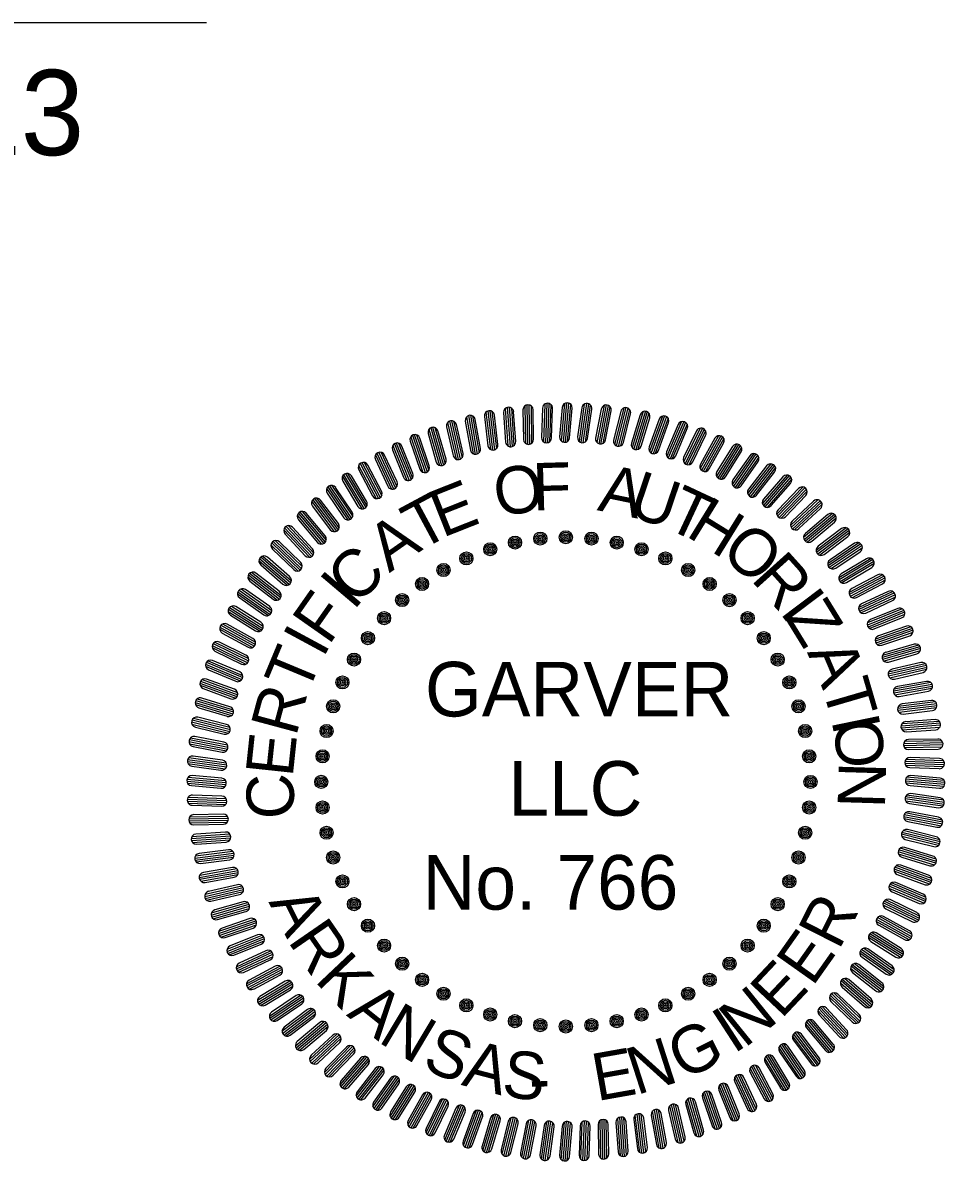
# Model space of a CAD drawing. Extents: x 1373884 to 1376992, y 1168426 to 1170473.
# Drawn here: x 1376215 to 1376507, y 1168433.5 to 1168793.9 of the extents above; entities that cross this region are included whole.
import ezdxf

# ---------------------------------------------------------------- set-up
doc = ezdxf.new("R2010")
doc.units = 0
for name, color, linetype in [('G-ANNO-STMP', 7, 'Continuous'), ('G-ANNO-TEXT', 7, 'Continuous'), ('R_Draft', 7, 'Continuous')]:
    doc.layers.add(name, color=color, linetype=linetype)

# ---------------------------------------------------------------- blocks, each defined once
blk = doc.blocks.new('SEALDO')
at = {"layer": 'G-ANNO-TEXT'}
for radius in [0.0396, 0.0305, 0.0213, 0.0122, 0.00305]:
    blk.add_circle((1.403, -0.4559), radius, dxfattribs=at)
blk = doc.blocks.new('SEALRI')
at = {"layer": 'G-ANNO-TEXT'}
for p, q in [((-0.0083, 2.2815), (-0.0281, 2.0555)), ((0.0043, 2.2859), (-0.0164, 2.049)), ((0.0164, 2.2848), (-0.0043, 2.0479)), ((0.0281, 2.2783), (0.0083, 2.0523)), ((-0.0226, 2.2583), (-0.0381, 2.0809)), ((0.0226, 2.0756), (0.0381, 2.253))]:
    blk.add_line(p, q, dxfattribs=at)
for centre, start, end in [((0.0078, 2.2556), 355, 175), ((-0.0078, 2.0782), 175, 355)]:
    blk.add_arc(centre, 0.0305, start, end, dxfattribs=at)

msp = doc.modelspace()

# ---------------------------------------------------------------- linework, layer by layer
at = {"layer": 'R_Draft'}
msp.add_line((1376273.16, 1168793.87), (1375919.94, 1168793.87), dxfattribs=at)

# ---------------------------------------------------------------- block references
at = {"layer": 'G-ANNO-STMP'}
for name, xscale, yscale, rotation in [('SEALRI', 52.492405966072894, 52.49240596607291, 9), ('SEALRI', 52.492405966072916, 52.49240596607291, 6), ('SEALRI', 52.492405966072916, 52.492405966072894, 3.0000000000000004), ('SEALRI', 52.49240596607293, 52.49240596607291, -2.9999999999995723), ('SEALRI', 52.4924059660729, 52.49240596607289, -5.9999999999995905), ('SEALRI', 52.492405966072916, 52.49240596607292, -8.999999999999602), ('SEALRI', 52.492405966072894, 52.4924059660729, 18), ('SEALRI', 52.4924059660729, 52.4924059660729, 15.000000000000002), ('SEALRI', 52.492405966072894, 52.492405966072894, 12.000000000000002), ('SEALRI', 52.492405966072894, 52.492405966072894, -11.999999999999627), ('SEALRI', 52.4924059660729, 52.492405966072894, -14.999999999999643), ('SEALRI', 52.4924059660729, 52.4924059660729, -17.999999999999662), ('SEALRI', 52.49240596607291, 52.4924059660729, 20.99999999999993), ('SEALRI', 52.4924059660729, 52.492405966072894, -20.999999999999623), ('SEALRI', 52.492405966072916, 52.492405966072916, 26.999999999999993), ('SEALRI', 52.49240596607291, 52.4924059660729, 23.99999999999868), ('SEALRI', 52.492405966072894, 52.4924059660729, -23.99999999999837), ('SEALRI', 52.492405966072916, 52.49240596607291, -26.9999999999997), ('SEALRI', 52.4924059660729, 52.492405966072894, 30.00000000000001), ('SEALRI', 52.4924059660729, 52.49240596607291, -29.99999999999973), ('SEALRI', 52.4924059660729, 52.492405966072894, 33), ('SEALRI', 52.4924059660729, 52.49240596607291, -32.999999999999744), ('SEALRI', 52.4924059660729, 52.492405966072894, 36), ('SEALRI', 52.4924059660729, 52.492405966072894, -35.999999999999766), ('SEALRI', 52.49240596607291, 52.4924059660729, 38.999999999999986), ('SEALRI', 52.4924059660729, 52.4924059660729, -38.99999999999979), ('SEALRI', 52.49240596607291, 52.4924059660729, 41.999999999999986), ('SEALRI', 52.4924059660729, 52.4924059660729, -41.99999999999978), ('SEALRI', 52.4924059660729, 52.492405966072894, 44.999999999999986), ('SEALRI', 52.49240596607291, 52.4924059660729, -44.99999999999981), ('SEALRI', 52.492405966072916, 52.49240596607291, 47.99999999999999), ('SEALDO', 52.4924059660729, 52.49240596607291, 113.99999999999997), ('SEALDO', 52.4924059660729, 52.49240596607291, 107.99999999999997), ('SEALDO', 52.4924059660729, 52.49240596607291, 101.99999999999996), ('SEALRI', 52.49240596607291, 52.4924059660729, -47.99999999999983), ('SEALRI', 52.49240596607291, 52.4924059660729, 50.99999999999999), ('SEALDO', 52.492405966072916, 52.492405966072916, 125.99999999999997), ('SEALDO', 52.492405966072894, 52.4924059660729, 119.99999999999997), ('SEALDO', 52.492405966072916, 52.49240596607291, 95.99999999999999), ('SEALDO', 52.49240596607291, 52.4924059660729, 90), ('SEALRI', 52.492405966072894, 52.4924059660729, -50.99999999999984), ('SEALRI', 52.4924059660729, 52.492405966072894, 54), ('SEALDO', 52.492405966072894, 52.49240596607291, 131.99999999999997), ('SEALDO', 52.492405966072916, 52.492405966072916, 83.99999999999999), ('SEALRI', 52.4924059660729, 52.4924059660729, -53.99999999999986), ('SEALDO', 52.4924059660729, 52.49240596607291, 138), ('SEALDO', 52.492405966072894, 52.4924059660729, 77.99999999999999), ('SEALRI', 52.49240596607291, 52.492405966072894, 56.99999999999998), ('SEALDO', 52.492405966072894, 52.4924059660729, 144), ('SEALDO', 52.492405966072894, 52.4924059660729, 72), ('SEALRI', 52.49240596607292, 52.49240596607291, -56.999999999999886), ('SEALRI', 52.492405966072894, 52.4924059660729, 59.999999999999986), ('SEALRI', 52.4924059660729, 52.4924059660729, -59.99999999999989), ('SEALDO', 52.49240596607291, 52.4924059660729, 150), ('SEALDO', 52.49240596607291, 52.49240596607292, 66.00000000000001), ('SEALRI', 52.492405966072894, 52.49240596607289, 63), ('SEALDO', 52.4924059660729, 52.49240596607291, 156.00000000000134), ('SEALDO', 52.49240596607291, 52.4924059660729, 60.00000000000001), ('SEALRI', 52.49240596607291, 52.492405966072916, -62.99999999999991), ('SEALRI', 52.49240596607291, 52.4924059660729, 65.99999999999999), ('SEALRI', 52.49240596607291, 52.49240596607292, -65.99999999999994), ('SEALDO', 52.492405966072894, 52.49240596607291, 162.00000000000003), ('SEALDO', 52.4924059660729, 52.492405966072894, 54), ('SEALRI', 52.49240596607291, 52.4924059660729, 68.99999999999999), ('SEALRI', 52.49240596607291, 52.4924059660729, -68.99999999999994), ('SEALRI', 52.492405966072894, 52.4924059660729, 72), ('SEALDO', 52.49240596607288, 52.4924059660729, 168.00000000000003), ('SEALDO', 52.49240596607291, 52.4924059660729, 48.000000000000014), ('SEALRI', 52.4924059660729, 52.4924059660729, -71.99999999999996), ('SEALRI', 52.4924059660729, 52.49240596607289, 75.00000000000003), ('SEALDO', 52.492405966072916, 52.49240596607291, 174.00000000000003), ('SEALDO', 52.492405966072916, 52.49240596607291, 42.00000000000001), ('SEALRI', 52.49240596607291, 52.4924059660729, -74.99999999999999), ('SEALRI', 52.492405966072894, 52.49240596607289, 78.00000000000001), ('SEALDO', 52.49240596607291, 52.4924059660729, -179.99999999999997), ('SEALDO', 52.4924059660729, 52.492405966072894, 36), ('SEALRI', 52.492405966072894, 52.492405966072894, -78), ('SEALRI', 52.492405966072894, 52.49240596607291, 81), ('SEALDO', 52.49240596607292, 52.49240596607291, -173.99999999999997), ('SEALDO', 52.49240596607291, 52.4924059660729, 29.999999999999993), ('SEALRI', 52.492405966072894, 52.49240596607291, -81.00000000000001), ('SEALRI', 52.492405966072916, 52.49240596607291, 84.00000000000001), ('SEALRI', 52.492405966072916, 52.49240596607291, -84.00000000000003), ('SEALDO', 52.492405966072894, 52.4924059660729, -167.99999999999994), ('SEALDO', 52.49240596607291, 52.4924059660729, 23.99999999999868), ('SEALRI', 52.4924059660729, 52.49240596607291, 87.00000000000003), ('SEALRI', 52.4924059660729, 52.4924059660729, -87.00000000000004), ('SEALRI', 52.49240596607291, 52.4924059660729, 90.00000000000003), ('SEALDO', 52.4924059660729, 52.492405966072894, -161.99999999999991), ('SEALDO', 52.492405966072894, 52.4924059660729, 18), ('SEALRI', 52.49240596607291, 52.4924059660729, -90.00000000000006), ('SEALRI', 52.492405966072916, 52.492405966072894, 93), ('SEALRI', 52.492405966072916, 52.49240596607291, -93.00000000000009), ('SEALDO', 52.4924059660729, 52.4924059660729, -156.00000000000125), ('SEALDO', 52.492405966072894, 52.492405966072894, 12.000000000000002), ('SEALRI', 52.492405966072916, 52.492405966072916, 96.00000000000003), ('SEALRI', 52.4924059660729, 52.492405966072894, -96.0000000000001), ('SEALRI', 52.49240596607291, 52.492405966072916, 99.00000000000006), ('SEALDO', 52.4924059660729, 52.49240596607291, -149.99999999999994), ('SEALDO', 52.492405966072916, 52.49240596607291, 6), ('SEALRI', 52.49240596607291, 52.492405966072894, -99.00000000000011), ('SEALRI', 52.492405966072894, 52.49240596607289, 102.00000000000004), ('SEALDO', 52.492405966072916, 52.49240596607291, -143.99999999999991), ('SEALRI', 52.492405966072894, 52.492405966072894, -102.00000000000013), ('SEALRI', 52.49240596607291, 52.4924059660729, 105.00000000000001), ('SEALRI', 52.49240596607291, 52.4924059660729, -105.00000000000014), ('SEALDO', 52.492405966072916, 52.49240596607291, -137.9999999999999), ('SEALDO', 52.4924059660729, 52.4924059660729, -6.000000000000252), ('SEALRI', 52.4924059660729, 52.4924059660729, 108.00000000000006), ('SEALRI', 52.49240596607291, 52.492405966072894, -108.00000000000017), ('SEALRI', 52.4924059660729, 52.492405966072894, 111.00000000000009), ('SEALDO', 52.4924059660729, 52.49240596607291, -131.99999999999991), ('SEALDO', 52.492405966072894, 52.492405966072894, -12.000000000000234), ('SEALRI', 52.4924059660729, 52.49240596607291, -111.00000000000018), ('SEALRI', 52.49240596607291, 52.492405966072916, 114.00000000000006), ('SEALDO', 52.4924059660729, 52.49240596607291, -125.9999999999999), ('SEALDO', 52.492405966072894, 52.4924059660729, -18.000000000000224), ('SEALRI', 52.49240596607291, 52.492405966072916, -114.0000000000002), ('SEALRI', 52.4924059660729, 52.49240596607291, 117.00000000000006), ('SEALRI', 52.49240596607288, 52.4924059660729, -117.00000000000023), ('SEALDO', 52.4924059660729, 52.4924059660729, -119.99999999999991), ('SEALDO', 52.49240596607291, 52.492405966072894, -23.999999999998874), ('SEALRI', 52.492405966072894, 52.4924059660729, 120.00000000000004), ('SEALDO', 52.4924059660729, 52.492405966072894, -30.00000000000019), ('SEALRI', 52.4924059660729, 52.4924059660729, -120.00000000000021), ('SEALRI', 52.4924059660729, 52.492405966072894, 123.00000000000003), ('SEALDO', 52.49240596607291, 52.492405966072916, -113.99999999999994), ('SEALRI', 52.492405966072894, 52.49240596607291, -123.00000000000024), ('SEALRI', 52.4924059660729, 52.49240596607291, 126.00000000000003), ('SEALDO', 52.4924059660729, 52.4924059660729, -107.99999999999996), ('SEALDO', 52.4924059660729, 52.4924059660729, -36.00000000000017), ('SEALRI', 52.4924059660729, 52.4924059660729, -126.00000000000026), ('SEALDO', 52.492405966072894, 52.49240596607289, -101.99999999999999), ('SEALDO', 52.4924059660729, 52.492405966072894, -42.00000000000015), ('SEALRI', 52.49240596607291, 52.4924059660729, 129.00000000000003), ('SEALDO', 52.492405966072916, 52.49240596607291, -96), ('SEALDO', 52.49240596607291, 52.492405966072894, -48.00000000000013), ('SEALRI', 52.492405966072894, 52.4924059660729, -129.00000000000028), ('SEALRI', 52.4924059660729, 52.4924059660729, 132), ('SEALDO', 52.49240596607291, 52.4924059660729, -90.00000000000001), ('SEALDO', 52.4924059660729, 52.4924059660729, -54.000000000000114), ('SEALRI', 52.49240596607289, 52.4924059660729, -132.00000000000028), ('SEALRI', 52.4924059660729, 52.49240596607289, 135), ('SEALDO', 52.492405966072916, 52.49240596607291, -84.00000000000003), ('SEALDO', 52.4924059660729, 52.49240596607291, -78.00000000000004), ('SEALDO', 52.4924059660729, 52.49240596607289, -72.00000000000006), ('SEALDO', 52.492405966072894, 52.49240596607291, -66.00000000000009), ('SEALDO', 52.4924059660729, 52.49240596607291, -60.0000000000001), ('SEALRI', 52.492405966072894, 52.4924059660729, -135.00000000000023), ('SEALRI', 52.4924059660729, 52.49240596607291, 138), ('SEALRI', 52.4924059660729, 52.492405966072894, -138.00000000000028), ('SEALRI', 52.492405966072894, 52.4924059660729, 140.99999999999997), ('SEALRI', 52.4924059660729, 52.4924059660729, -141.0000000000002), ('SEALRI', 52.492405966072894, 52.4924059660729, 144), ('SEALRI', 52.49240596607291, 52.49240596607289, -144.00000000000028), ('SEALRI', 52.4924059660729, 52.492405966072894, 146.99999999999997), ('SEALRI', 52.4924059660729, 52.49240596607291, -147.00000000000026), ('SEALRI', 52.4924059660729, 52.49240596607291, 149.99999999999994), ('SEALRI', 52.49240596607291, 52.492405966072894, -150.00000000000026), ('SEALRI', 52.492405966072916, 52.49240596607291, 152.99999999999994), ('SEALRI', 52.4924059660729, 52.49240596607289, 156.00000000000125), ('SEALRI', 52.492405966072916, 52.49240596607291, -156.00000000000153), ('SEALRI', 52.4924059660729, 52.49240596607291, -153.00000000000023), ('SEALRI', 52.4924059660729, 52.4924059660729, 159), ('SEALRI', 52.4924059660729, 52.49240596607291, -159.00000000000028), ('SEALRI', 52.49240596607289, 52.49240596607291, 161.99999999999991), ('SEALRI', 52.4924059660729, 52.49240596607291, 164.99999999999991), ('SEALRI', 52.492405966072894, 52.49240596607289, 167.99999999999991), ('SEALRI', 52.492405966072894, 52.4924059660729, -168.0000000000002), ('SEALRI', 52.4924059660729, 52.49240596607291, -165.0000000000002), ('SEALRI', 52.4924059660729, 52.4924059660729, -162.0000000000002), ('SEALRI', 52.49240596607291, 52.492405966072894, 170.9999999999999), ('SEALRI', 52.4924059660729, 52.4924059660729, 173.9999999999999), ('SEALRI', 52.492405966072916, 52.49240596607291, 176.9999999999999), ('SEALRI', 52.49240596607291, 52.4924059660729, 179.99999999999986), ('SEALRI', 52.492405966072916, 52.49240596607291, -177.00000000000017), ('SEALRI', 52.4924059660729, 52.492405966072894, -174.00000000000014), ('SEALRI', 52.49240596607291, 52.49240596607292, -171.00000000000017)]:
    msp.add_blockref(name, (1376386.93, 1168553.57), dxfattribs=dict(at, xscale=xscale, yscale=yscale, rotation=rotation))
at = {"layer": 'G-ANNO-STMP', "xscale": 52.49240596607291, "yscale": 52.4924059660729}
for name in ['SEALRI', 'SEALDO']:
    msp.add_blockref(name, (1376386.93, 1168553.57), dxfattribs=at)

# ---------------------------------------------------------------- texts
at = {"layer": 'G-ANNO-STMP'}
for s, rotation, p in [('O', 8.2771, (1376365.2, 1168637.52)), ('F', 1.6104, (1376376.57, 1168639.47)), ('A', 348.2771, (1376396.62, 1168639.6)), ('U', 341.2772, (1376406, 1168638.1)), ('E', 21.6104, (1376347.83, 1168630.76)), ('T', 334.9438, (1376417.79, 1168634.3)), ('T', 28.2771, (1376340.58, 1168626.52)), ('H', 328.2771, (1376424.54, 1168631.63)), ('A', 34.9438, (1376331.04, 1168619.62)), ('O', 319.7874, (1376435.39, 1168625.47)), ('C', 44.3881, (1376320.41, 1168609.05)), ('R', 311.9933, (1376445.22, 1168617.62)), ('I', 49.7408, (1376319.64, 1168607.51)), ('F', 54.9438, (1376311.83, 1168596.52)), ('I', 307.0081, (1376454.38, 1168607.33)), ('Z', 301.6104, (1376456.14, 1168605.52)), ('I', 61.6104, (1376310.05, 1168592.47)), ('T', 67.4314, (1376305, 1168580.85)), ('A', 292.9752, (1376463.21, 1168594.63)), ('T', 286.3085, (1376467.91, 1168583.77)), ('R', 74.9438, (1376301.49, 1168567.64)), ('I', 281.6104, (1376470.92, 1168573.22)), ('O', 276.4823, (1376471.5, 1168572.68)), ('E', 83.8985, (1376300.42, 1168554.81)), ('N', 268.2771, (1376473.37, 1168560.02)), ('C', 91.8842, (1376301.09, 1168542.01)), ('A', 296.5747, (1376292.76, 1168515.57)), ('R', 63.0959, (1376473.34, 1168500.01)), ('R', 304.6183, (1376298.68, 1168503.22)), ('E', 54.7309, (1376465, 1168488.49)), ('K', 313.3805, (1376307.1, 1168490.67)), ('E', 46.6807, (1376455.07, 1168478.25)), ('N', 38.9821, (1376443.47, 1168469.08)), ('A', 321.2584, (1376317.24, 1168479.71)), ('N', 329.1099, (1376327.11, 1168471.41)), ('I', 32.979, (1376440, 1168467.3)), ('S', 337.6294, (1376340.95, 1168462.97)), ('G', 26.4132, (1376424.08, 1168458.94)), ('A', 345.4073, (1376353.57, 1168457.67)), ('N', 17.8686, (1376409.3, 1168454.35)), ('S', 352.8046, (1376366.3, 1168454.1)), ('E', 10.0695, (1376396.74, 1168452.49)), ('-', 0.8385, (1376375.36, 1168452.14))]:
    msp.add_text(s, height=15, rotation=rotation, dxfattribs=at).set_placement(p)
for s, p in [('GARVER', (1376342.35, 1168574.29)), ('LLC', (1376368.76, 1168542.86)), ('No. 766', (1376341.6, 1168513.13))]:
    msp.add_text(s, height=17.279, dxfattribs=at).set_placement(p)
at = {"layer": 'R_Draft'}
msp.add_text('END JOB 020713', height=27, dxfattribs=at).set_placement((1375947.46, 1168751.96))

doc.saveas('drawing.dxf')
